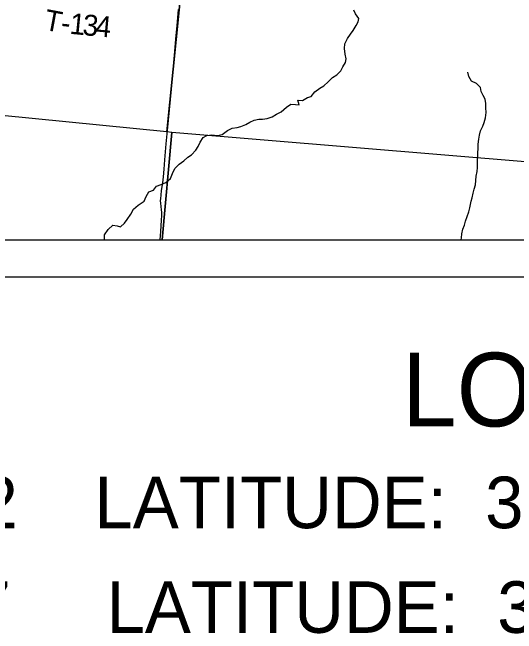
# Model space of a CAD drawing. Extents: x 0 to 34, y 0 to 22.
# Drawn here: x 3.369 to 4.739, y 13.032 to 14.717 of the extents above; entities that cross this region are included whole.
import ezdxf

# ---------------------------------------------------------------- set-up
doc = ezdxf.new("R2010")
doc.units = 0
for name, color, linetype in [('Default', 7, 'Continuous'), ('GM_X_City_Street', 7, 'Continuous'), ('GM_X_Minor_River', 7, 'Continuous'), ('GM_X_Section', 7, 'Continuous'), ('GM_X_Township_Road', 7, 'Continuous'), ('GM_X_Township_Road_Text', 7, 'Continuous'), ('SH_Data', 7, 'Continuous'), ('SH_Text', 7, 'Continuous')]:
    doc.layers.add(name, color=color, linetype=linetype)

msp = doc.modelspace()

# ---------------------------------------------------------------- linework, layer by layer
at = {"layer": 'Default'}
for points in [[(2.7639, 14.1), (3.7756, 14.1), (3.8021, 14.3916), (3.7885, 14.3929), (2.8001, 14.4908)], [(3.7756, 14.1), (4.7807, 14.1), (4.7952, 14.3092), (4.7835, 14.3098), (3.8021, 14.3916)]]:
    msp.add_lwpolyline(points, close=True, dxfattribs=at)
at = {"layer": 'GM_X_City_Street'}
msp.add_lwpolyline([(2.1, 15.6775), (2.1, 14.1), (6.8413, 14.1), (6.8442, 14.1329), (6.8121, 14.1362), (6.8413, 14.4929), (6.9742, 15.9512)], dxfattribs=at)
at = {"layer": 'GM_X_Minor_River'}
for points in [[(4.2713, 14.619), (4.2723, 14.632), (4.2797, 14.646), (4.287, 14.6584), (4.2947, 14.6682), (4.3025, 14.6814), (4.3079, 14.6912), (4.31, 14.7007), (4.301, 14.7133), (4.2966, 14.7232)], [(3.6196, 14.1), (3.6196, 14.1001), (3.6194, 14.1137), (3.6291, 14.1276), (3.6417, 14.14), (3.6534, 14.1383), (3.6632, 14.1355), (3.6739, 14.1453), (3.6808, 14.1554), (3.6908, 14.1693), (3.6978, 14.1828), (3.7111, 14.1937), (3.7272, 14.2048), (3.7322, 14.2173), (3.7396, 14.2305), (3.7528, 14.2345), (3.7609, 14.2453), (3.7734, 14.2501), (3.786, 14.256), (3.7986, 14.2665), (3.8044, 14.2801), (3.8106, 14.2932), (3.8225, 14.3056), (3.8347, 14.3145), (3.8458, 14.3239), (3.8557, 14.3306), (3.8672, 14.3437), (3.8738, 14.3535), (3.8796, 14.3651), (3.8877, 14.3779), (3.8972, 14.3835), (3.9104, 14.3848), (3.9263, 14.3831), (3.9392, 14.386), (3.9537, 14.3968), (3.9662, 14.4027), (3.9795, 14.4052), (3.9897, 14.4074), (4.003, 14.4129), (4.014, 14.4192), (4.0258, 14.4251), (4.0383, 14.4272), (4.0482, 14.4275), (4.0607, 14.4296), (4.0751, 14.434), (4.0865, 14.441), (4.0991, 14.4473), (4.1132, 14.4604), (4.1258, 14.4682), (4.1378, 14.4669), (4.148, 14.4664), (4.1444, 14.4794), (4.1573, 14.4784), (4.171, 14.4866), (4.1805, 14.4888), (4.1908, 14.5012), (4.2038, 14.5116), (4.2152, 14.5179), (4.2267, 14.5288), (4.2382, 14.5404), (4.2504, 14.5478), (4.2611, 14.5586), (4.2669, 14.5696), (4.2742, 14.5808), (4.2755, 14.5911), (4.2726, 14.604), (4.2713, 14.619)], [(4.5968, 14.1397), (4.5996, 14.1502), (4.6043, 14.1634), (4.6086, 14.1763), (4.6118, 14.1868), (4.6154, 14.2046), (4.6181, 14.2144), (4.6209, 14.2265), (4.6237, 14.2378), (4.6265, 14.2496), (4.6282, 14.2613), (4.6287, 14.2723), (4.6315, 14.2855), (4.632, 14.2961), (4.6326, 14.3097), (4.6329, 14.3344), (4.6338, 14.3495), (4.6343, 14.3593), (4.6364, 14.3733), (4.638, 14.3843), (4.6408, 14.3956), (4.6466, 14.4085), (4.6501, 14.4183), (4.6541, 14.4311), (4.6558, 14.4451), (4.6552, 14.4584), (4.6549, 14.4697), (4.6528, 14.4819), (4.6477, 14.4914), (4.6425, 14.5029), (4.6407, 14.5135), (4.6292, 14.5242), (4.616, 14.5305), (4.609, 14.5434), (4.6061, 14.5552)], [(4.5879, 14.1), (4.5885, 14.1057), (4.5897, 14.1159), (4.5925, 14.1287), (4.5968, 14.1397)]]:
    msp.add_lwpolyline(points, dxfattribs=at)
at = {"layer": 'GM_X_Section'}
for points in [[(2.8777, 15.4895), (3.89, 15.3957), (3.7885, 14.3929), (2.8001, 14.4908), (2.7782, 14.493)], [(3.89, 15.3957), (4.8743, 15.3051), (4.7835, 14.3098), (3.8021, 14.3916), (3.7885, 14.3929)]]:
    msp.add_lwpolyline(points, close=True, dxfattribs=at)
at = {"layer": 'GM_X_Township_Road'}
msp.add_lwpolyline([(3.7701, 14.1), (3.7719, 14.1224), (3.7745, 14.1533), (3.7751, 14.1657), (3.7749, 14.1749), (3.7745, 14.181), (3.7733, 14.1902), (3.7721, 14.1995), (3.7718, 14.2058), (3.772, 14.212), (3.7728, 14.2213), (3.7745, 14.2337), (3.7779, 14.2551), (3.7796, 14.2705), (3.7814, 14.2921), (3.7831, 14.3169), (3.7868, 14.3601), (3.7894, 14.3879), (3.7932, 14.425), (3.7959, 14.4528), (3.7983, 14.4807), (3.801, 14.5085), (3.8034, 14.5332), (3.8056, 14.5611), (3.8091, 14.6013), (3.813, 14.6446), (3.8164, 14.6817), (3.8206, 14.725)], dxfattribs=at)
at = {"layer": 'SH_Data'}
for p, q in [((2.1, 14.1), (8.9, 14.1)), ((2, 14), (9, 14))]:
    msp.add_line(p, q, dxfattribs=at)

# ---------------------------------------------------------------- texts
at = {"layer": 'GM_X_Township_Road_Text'}
for s, rotation, p in [('T', 349.4293, (3.4526, 14.6703)), ('1', 354.4875, (3.523, 14.6593)), ('3', 354.725, (3.5581, 14.6559)), ('4', 354.7906, (3.593, 14.6527)), ('-', 354.0048, (3.4992, 14.6618))]:
    msp.add_text(s, height=0.0568, rotation=rotation, dxfattribs=at).set_placement(p)
at = {"layer": 'SH_Text'}
for s, height, p in [('LOCATION MAP', 0.2, (4.4269, 13.5937)), ('CLA-40-0732    LATITUDE:  39°55\'18"    LONGITUDE:  83°54\'42"', 0.14, (2.2704, 13.3175)), ('CLA-40-0757     LATITUDE:  39°55\'20"     LONGITUDE:  83°54\'25"', 0.14, (2.2512, 13.0335))]:
    msp.add_text(s, height=height, dxfattribs=at).set_placement(p)

doc.saveas('drawing.dxf')
